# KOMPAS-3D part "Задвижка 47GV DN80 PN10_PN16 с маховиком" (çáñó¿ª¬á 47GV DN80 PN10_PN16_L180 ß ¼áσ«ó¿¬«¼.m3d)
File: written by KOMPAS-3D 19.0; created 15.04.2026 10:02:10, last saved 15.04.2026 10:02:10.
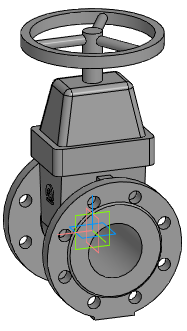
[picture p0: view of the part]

Document properties: Автор: Евгений; Полное имя файла: Z:\3.Личные\kachalov\3d для проектировщиков\2.1 Тип 47GV, 47GV.Z\Задвижка 47GV_DN40-DN600\stp_Задвижка 47GV\Задвижка 47GV DN80 PN10_PN16_L180 с маховиком.m3d

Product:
- Part/product: Задвижка 47GV DN80 PN10_PN16 с маховиком

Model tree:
1. Операция без истории:1  (labels: Задвижка 47GV DN80 PN10_PN16 с маховиком)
